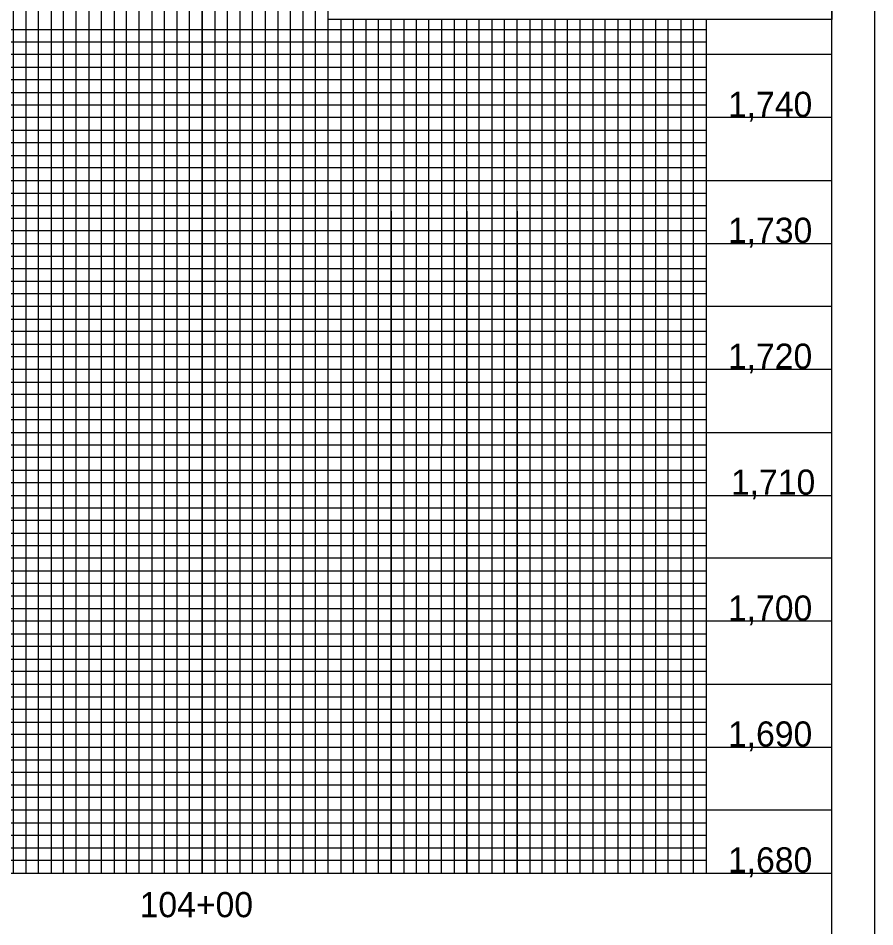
# Model space of a CAD drawing. Extents: x 505602 to 507286, y 483109 to 484209.
# Drawn here: x 506946 to 507286.1, y 483662.4 to 484023.2 of the extents above; entities that cross this region are included whole.
import ezdxf

# ---------------------------------------------------------------- set-up
doc = ezdxf.new("R2010")
doc.units = 0
for name, color, linetype in [('Exist Vertical Profile Vertical Axis Label', 7, 'Continuous'), ('Sheet Layout Profile Border Port 1', 7, 'Continuous'), ('Sheet Plot Border Outside CELL', 7, 'Continuous'), ('Sheet Profile CELL', 7, 'Continuous'), ('Sheet Profile Grid Major CELL', 7, 'Continuous'), ('Sheet Profile Grid Middle CELL', 7, 'Continuous'), ('Sheet Profile Grid Minor CELL', 7, 'Continuous'), ('Sheet Sticker Exception Certification CELL', 7, 'Continuous')]:
    doc.layers.add(name, color=color, linetype=linetype)

msp = doc.modelspace()

# ---------------------------------------------------------------- linework, layer by layer
at = {"layer": 'Sheet Layout Profile Border Port 1'}
msp.add_lwpolyline([(505819.08, 484183.71), (505819.08, 483683.71), (507019.08, 483683.71), (507019.08, 484022.66), (507019.08, 484022.66), (507019.08, 484183.71)], close=True, dxfattribs=at)
at = {"layer": 'Sheet Plot Border Outside CELL'}
msp.add_lwpolyline([(505602.08, 483108.71), (507286.08, 483108.71), (507286.08, 484208.71), (505602.08, 484208.71)], close=True, dxfattribs=at)
at = {"layer": 'Sheet Profile CELL'}
msp.add_line((505769.08, 483683.71), (507269.08, 483683.71), dxfattribs=at)
msp.add_lwpolyline([(507269.08, 484183.71), (505769.08, 484183.71), (505769.08, 483133.71), (507269.08, 483133.71)], close=True, dxfattribs=at)
at = {"layer": 'Sheet Profile Grid Major CELL'}
for points in [[(506519.08, 483683.71), (506569.08, 483683.71), (506569.08, 484183.71), (506619.08, 484183.71), (506619.08, 483683.71), (506669.08, 483683.71), (506669.08, 484183.71), (506719.08, 484183.71), (506719.08, 483683.71), (506769.08, 483683.71), (506769.08, 484183.71), (506819.08, 484183.71), (506819.08, 483683.71), (506869.08, 483683.71), (506869.08, 484183.71), (506919.08, 484183.71), (506919.08, 483683.71), (506969.08, 483683.71), (506969.08, 484183.71), (507019.08, 484183.71), (507019.08, 483683.71), (507069.08, 483683.71), (507069.08, 484183.71), (507095.38, 484183.71)], [(507219.08, 484022.66), (507219.08, 483683.71), (507269.08, 483683.71), (507269.08, 484033.71)], [(507119.08, 484022.66), (507119.08, 483683.71), (507169.08, 483683.71), (507169.08, 483683.71), (507169.08, 484022.66)], [(507269.08, 483983.71), (505769.08, 483983.71), (505769.08, 483933.71), (507269.08, 483933.71)], [(507269.08, 483883.71), (505769.08, 483883.71), (505769.08, 483833.71), (507269.08, 483833.71)], [(507269.08, 483783.71), (505769.08, 483783.71), (505769.08, 483783.71), (505769.08, 483733.71), (507269.08, 483733.71)]]:
    msp.add_lwpolyline(points, dxfattribs=at)
at = {"layer": 'Sheet Profile Grid Middle CELL'}
for points in [[(506544.08, 483683.71), (506594.08, 483683.71), (506594.08, 484183.71), (506644.08, 484183.71), (506644.08, 483683.71), (506694.08, 483683.71), (506694.08, 484183.71), (506744.08, 484183.71), (506744.08, 483683.71), (506794.08, 483683.71), (506794.08, 484183.71), (506844.08, 484183.71), (506844.08, 483683.71), (506894.08, 483683.71), (506894.08, 484183.71), (506944.08, 484183.71), (506944.08, 483683.71), (506994.08, 483683.71), (506994.08, 484183.71), (507044.08, 484183.71), (507044.08, 483683.71), (507094.08, 483683.71), (507094.08, 484022.66)], [(507094.08, 483946.51), (507094.08, 483683.71), (507144.08, 483683.71), (507144.08, 484022.66)], [(507144.08, 483946.51), (507144.08, 483683.71), (507194.08, 483683.71), (507194.08, 484022.66)], [(507269.08, 484008.71), (505769.08, 484008.71), (505769.08, 483958.71), (507094.08, 483958.71)], [(507094.08, 483958.71), (507269.08, 483958.71)], [(507269.08, 483908.71), (505769.08, 483908.71), (505769.08, 483858.71), (507269.08, 483858.71)], [(507269.08, 483808.71), (505769.08, 483808.71), (505769.08, 483758.71), (507269.08, 483758.71)], [(507269.08, 483708.71), (505769.08, 483708.71)]]:
    msp.add_lwpolyline(points, dxfattribs=at)
at = {"layer": 'Sheet Profile Grid Minor CELL'}
for p, q in [((505819.08, 484018.71), (507219.08, 484018.71)), ((507219.08, 483998.71), (505819.08, 483998.71)), ((505819.08, 483993.71), (507219.08, 483993.71)), ((507219.08, 483973.71), (505819.08, 483973.71)), ((505819.08, 483968.71), (507219.08, 483968.71)), ((507219.08, 483948.71), (505819.08, 483948.71)), ((505819.08, 483943.71), (507219.08, 483943.71)), ((507219.08, 483938.71), (505819.08, 483938.71)), ((505819.08, 483928.71), (507219.08, 483928.71)), ((507219.08, 483923.71), (505819.08, 483923.71)), ((505819.08, 483918.71), (507219.08, 483918.71)), ((507219.08, 483913.71), (505819.08, 483913.71)), ((505819.08, 483903.71), (507219.08, 483903.71)), ((507219.08, 483898.71), (505819.08, 483898.71)), ((505819.08, 483893.71), (507219.08, 483893.71)), ((507219.08, 483888.71), (505819.08, 483888.71)), ((505819.08, 483878.71), (507219.08, 483878.71)), ((507219.08, 483873.71), (505819.08, 483873.71)), ((505819.08, 483868.71), (507219.08, 483868.71)), ((507219.08, 483863.71), (505819.08, 483863.71)), ((505819.08, 483853.71), (507219.08, 483853.71)), ((507219.08, 483848.71), (505819.08, 483848.71)), ((505819.08, 483843.71), (507219.08, 483843.71)), ((507219.08, 483838.71), (505819.08, 483838.71)), ((505819.08, 483828.71), (507219.08, 483828.71)), ((507219.08, 483823.71), (505819.08, 483823.71)), ((505819.08, 483818.71), (507219.08, 483818.71)), ((507219.08, 483813.71), (505819.08, 483813.71)), ((505819.08, 483803.71), (507219.08, 483803.71)), ((507219.08, 483798.71), (505819.08, 483798.71)), ((507219.08, 483793.71), (505819.08, 483793.71)), ((507219.08, 483788.71), (505819.08, 483788.71)), ((505819.08, 483778.71), (507219.08, 483778.71)), ((507219.08, 483773.71), (505819.08, 483773.71)), ((505819.08, 483768.71), (507219.08, 483768.71)), ((507219.08, 483763.71), (505819.08, 483763.71)), ((505819.08, 483753.71), (507219.08, 483753.71)), ((507219.08, 483748.71), (505819.08, 483748.71)), ((505819.08, 483743.71), (507219.08, 483743.71)), ((507219.08, 483738.71), (505819.08, 483738.71)), ((505819.08, 483728.71), (507219.08, 483728.71)), ((507219.08, 483723.71), (505819.08, 483723.71)), ((505819.08, 483718.71), (507219.08, 483718.71)), ((507219.08, 483713.71), (505819.08, 483713.71)), ((505819.08, 483703.71), (507219.08, 483703.71)), ((507219.08, 483698.71), (505819.08, 483698.71)), ((505819.08, 483693.71), (507219.08, 483693.71))]:
    msp.add_line(p, q, dxfattribs=at)
for points in [[(506939.08, 484183.71), (506949.08, 484183.71), (506949.08, 483683.71), (506954.08, 483683.71), (506954.08, 484183.71), (506959.08, 484183.71), (506959.08, 483683.71)], [(506959.08, 483683.71), (506964.08, 483683.71), (506964.08, 484183.71)], [(506974.08, 484183.71), (506974.08, 483683.71), (506979.08, 483683.71), (506979.08, 484183.71)], [(506984.08, 484183.71), (506984.08, 483683.71), (506989.08, 483683.71), (506989.08, 484183.71)], [(506999.08, 484183.71), (506999.08, 483683.71), (507004.08, 483683.71), (507004.08, 484183.71)], [(507009.08, 484183.71), (507009.08, 483683.71), (507014.08, 483683.71), (507014.08, 484183.71)], [(507024.08, 484183.71), (507024.08, 483683.71), (507029.08, 483683.71), (507029.08, 484183.71)], [(507034.08, 484183.71), (507034.08, 483683.71), (507039.08, 483683.71), (507039.08, 484183.71)], [(507049.08, 484183.71), (507049.08, 483683.71), (507054.08, 483683.71), (507054.08, 484183.71)], [(507059.08, 484183.71), (507059.08, 483683.71), (507064.08, 483683.71), (507064.08, 484183.71)], [(507074.08, 484022.66), (507074.08, 483683.71), (507079.08, 483683.71), (507079.08, 484022.66)], [(507084.08, 484022.66), (507084.08, 483683.71), (507089.08, 483683.71), (507089.08, 484022.66)], [(507099.08, 484022.66), (507099.08, 483683.71), (507099.08, 483683.71), (507104.08, 483683.71), (507109.08, 483683.71), (507109.08, 484022.66)], [(507104.08, 484022.66), (507104.08, 483683.71)], [(507114.07, 484022.66), (507113.98, 483683.76), (507118.98, 483683.76), (507124.08, 483683.71), (507124.08, 484022.66)], [(507124.08, 483946.51), (507124.08, 483683.71), (507129.08, 483683.71), (507129.08, 484022.66)], [(507134.08, 484022.66), (507134.08, 483683.71), (507139.08, 483683.71), (507139.08, 484022.66)], [(507149.08, 484022.66), (507149.08, 483683.71), (507154.08, 483683.71), (507154.08, 484022.66)], [(507159.08, 484022.66), (507159.08, 483683.71), (507164.08, 483683.71), (507164.08, 484022.66)], [(507174.08, 484022.66), (507174.08, 483683.71), (507179.08, 483683.71), (507179.08, 484022.66)], [(507184.08, 484022.66), (507184.08, 483683.71), (507189.08, 483683.71), (507189.08, 484022.66)], [(507199.08, 484022.66), (507199.08, 483683.71), (507204.08, 483683.71), (507204.08, 484022.66)], [(507209.08, 484022.66), (507209.08, 483683.71), (507214.08, 483683.71), (507214.08, 484022.66)], [(507219.08, 484013.71), (505819.08, 484013.71), (505819.08, 484003.71), (507219.08, 484003.71)], [(507219.08, 483988.71), (505819.08, 483988.71), (505819.08, 483978.71), (507219.08, 483978.71)], [(507219.08, 483963.71), (505819.08, 483963.71), (505819.08, 483953.71), (507219.08, 483953.71)], [(507219.08, 483688.71), (505819.08, 483688.71)]]:
    msp.add_lwpolyline(points, dxfattribs=at)
at = {"layer": 'Sheet Sticker Exception Certification CELL'}
for p, q in [((507069.03, 484022.66), (507069.03, 484046.16)), ((507069.03, 484022.66), (507069.03, 484046.16)), ((507269.07, 484046.15), (507269.07, 484022.65)), ((507269.07, 484046.15), (507269.07, 484022.65)), ((507269.07, 484022.66), (507069.03, 484022.66)), ((507269.07, 484022.66), (507069.03, 484022.66))]:
    msp.add_line(p, q, dxfattribs=at)

# ---------------------------------------------------------------- texts
at = {"layer": 'Exist Vertical Profile Vertical Axis Label'}
for s, p in [('1,740', (507227.78, 483983.96)), ('1,730', (507227.78, 483933.96)), ('1,720', (507227.78, 483883.96)), ('1,710', (507228.97, 483833.96)), ('1,700', (507227.78, 483783.96)), ('1,690', (507227.78, 483733.96)), ('1,680', (507227.78, 483683.96)), ('104+00', (506994.26, 483666.21))]:
    msp.add_text(s, height=10, dxfattribs=at).set_placement(p)

doc.saveas('drawing.dxf')
